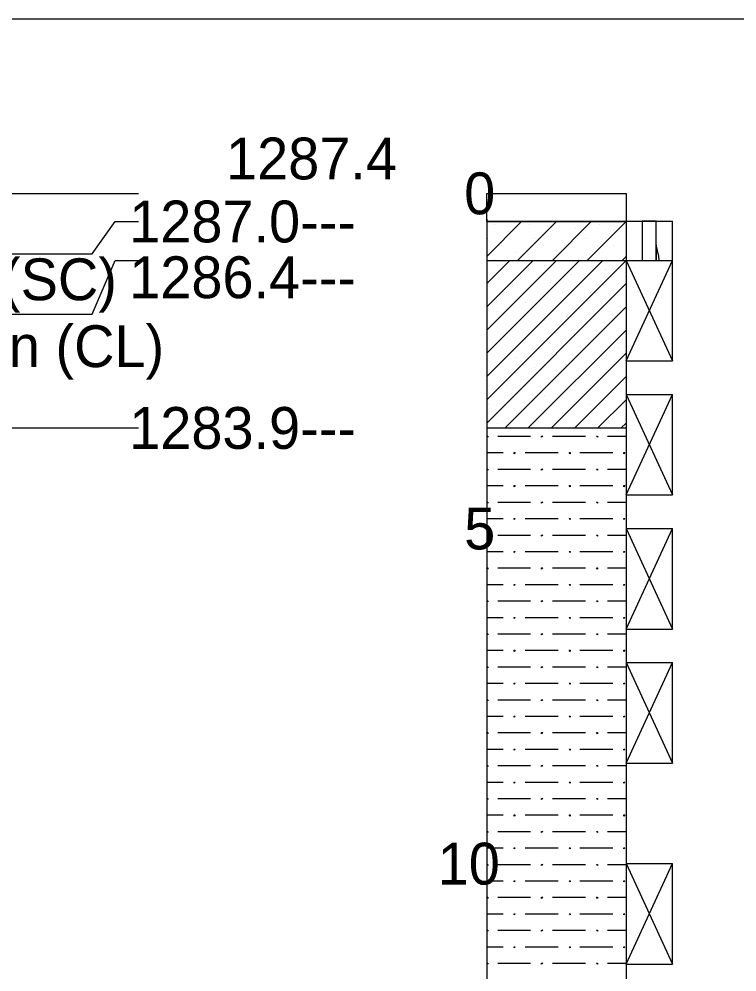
# Model space of a CAD drawing. Extents: x 2150148.6 to 2150220.1, y 143803.7 to 143875.1.
# Drawn here: x 2150200.808 to 2150203.385, y 143855.669 to 143859.086 of the extents above; entities that cross this region are included whole.
import ezdxf

# ---------------------------------------------------------------- set-up
doc = ezdxf.new("R2010")
doc.units = 0
doc.layers.add('Default', color=7, linetype='Continuous')

# ---------------------------------------------------------------- blocks, each defined once
blk = doc.blocks.new('POINT_DISPLAY')
at = {"layer": 'Default'}
blk.add_line((0, 0), (0, 0), dxfattribs=at)

msp = doc.modelspace()

# ---------------------------------------------------------------- linework, layer by layer
at = {"layer": 'Default'}
for points in [[(2150197.0699, 143858.4608), (2150201.2366, 143858.4608)], [(2150197.0699, 143858.3599), (2150197.1532, 143858.3599), (2150197.2366, 143858.2442), (2150201.0699, 143858.2442), (2150201.1532, 143858.3599), (2150201.2366, 143858.3599)], [(2150202.4866, 143858.3678), (2150202.4866, 143846.4416)], [(2150202.4866, 143858.3599), (2150202.9866, 143858.3599)], [(2150202.4866, 143858.2349), (2150202.6116, 143858.3599)], [(2150202.5971, 143858.2204), (2150202.7366, 143858.3599)], [(2150202.7221, 143858.2204), (2150202.8616, 143858.3599)], [(2150202.8471, 143858.2204), (2150202.9866, 143858.3599)], [(2150202.9866, 143858.3606), (2150203.1532, 143858.3606)], [(2150202.9866, 143858.3606), (2150202.9866, 143846.4416)], [(2150203.1532, 143858.2204), (2150203.1532, 143858.3606)], [(2150202.9721, 143858.2204), (2150202.9866, 143858.2349)], [(2150197.0699, 143858.2204), (2150197.1532, 143858.2204), (2150197.2366, 143858.0275), (2150201.0699, 143858.0275), (2150201.1532, 143858.2204), (2150201.2366, 143858.2204)], [(2150202.4866, 143858.2204), (2150202.9866, 143858.2204)], [(2150202.4866, 143858.1371), (2150202.5699, 143858.2204)], [(2150202.4866, 143858.0538), (2150202.6532, 143858.2204)], [(2150202.4866, 143857.9704), (2150202.7366, 143858.2204)], [(2150202.4866, 143857.8871), (2150202.8199, 143858.2204)], [(2150202.4866, 143857.8038), (2150202.9032, 143858.2204)], [(2150202.4866, 143857.7204), (2150202.9866, 143858.2204)], [(2150202.9866, 143858.2204), (2150203.1532, 143858.2204)], [(2150202.9866, 143858.2204), (2150203.1532, 143857.8599)], [(2150202.9866, 143857.8599), (2150203.1532, 143858.2204)], [(2150202.9866, 143858.2204), (2150203.1532, 143858.2204)], [(2150203.1532, 143857.8599), (2150203.1532, 143858.2204)], [(2150202.4866, 143857.6371), (2150202.9866, 143858.1371)], [(2150202.5523, 143857.6195), (2150202.9866, 143858.0538)], [(2150202.6356, 143857.6195), (2150202.9866, 143857.9704)], [(2150202.7189, 143857.6195), (2150202.9866, 143857.8871)], [(2150202.9866, 143857.8599), (2150203.1532, 143857.8599)], [(2150202.8023, 143857.6195), (2150202.9866, 143857.8038)], [(2150202.8856, 143857.6195), (2150202.9866, 143857.7204)], [(2150202.9866, 143857.7397), (2150203.1532, 143857.3791)], [(2150202.9866, 143857.3791), (2150203.1532, 143857.7397)], [(2150202.9866, 143857.7397), (2150203.1532, 143857.7397)], [(2150203.1532, 143857.3791), (2150203.1532, 143857.7397)], [(2150197.0699, 143857.6195), (2150201.2366, 143857.6195)], [(2150202.4866, 143857.6195), (2150202.9866, 143857.6195)], [(2150202.9689, 143857.6195), (2150202.9866, 143857.6371)], [(2150202.4866, 143857.59), (2150202.4905, 143857.59), (2150202.4905, 143857.586), (2150202.4866, 143857.59)], [(2150202.5259, 143857.59), (2150202.644, 143857.59)], [(2150202.6834, 143857.59), (2150202.6874, 143857.59), (2150202.6834, 143857.586), (2150202.6834, 143857.59)], [(2150202.7228, 143857.59), (2150202.8409, 143857.59)], [(2150202.8803, 143857.59), (2150202.8842, 143857.59), (2150202.8842, 143857.586), (2150202.8803, 143857.59)], [(2150202.9196, 143857.59), (2150202.9866, 143857.59)], [(2150202.4866, 143857.5309), (2150202.5456, 143857.5309)], [(2150202.585, 143857.5309), (2150202.5889, 143857.5309), (2150202.585, 143857.527), (2150202.585, 143857.5309)], [(2150202.6244, 143857.5309), (2150202.7425, 143857.5309)], [(2150202.7818, 143857.5309), (2150202.7858, 143857.5309), (2150202.7858, 143857.527), (2150202.7818, 143857.5309)], [(2150202.8212, 143857.5309), (2150202.8803, 143857.5309)], [(2150202.8803, 143857.5309), (2150202.9393, 143857.5309)], [(2150202.9787, 143857.5309), (2150202.9826, 143857.5309), (2150202.9787, 143857.527), (2150202.9787, 143857.5309)], [(2150202.4866, 143857.4718), (2150202.4905, 143857.4718), (2150202.4905, 143857.4679), (2150202.4866, 143857.4718)], [(2150202.5259, 143857.4718), (2150202.644, 143857.4718)], [(2150202.6834, 143857.4718), (2150202.6874, 143857.4718), (2150202.6834, 143857.4679), (2150202.6834, 143857.4718)], [(2150202.7228, 143857.4718), (2150202.8409, 143857.4718)], [(2150202.8803, 143857.4718), (2150202.8842, 143857.4718), (2150202.8842, 143857.4679), (2150202.8803, 143857.4718)], [(2150202.9196, 143857.4718), (2150202.9866, 143857.4718)], [(2150202.4866, 143857.4128), (2150202.5456, 143857.4128)], [(2150202.585, 143857.4128), (2150202.5889, 143857.4128), (2150202.585, 143857.4089), (2150202.585, 143857.4128)], [(2150202.6244, 143857.4128), (2150202.7425, 143857.4128)], [(2150202.7818, 143857.4128), (2150202.7858, 143857.4128), (2150202.7858, 143857.4089), (2150202.7818, 143857.4128)], [(2150202.8212, 143857.4128), (2150202.8803, 143857.4128)], [(2150202.8803, 143857.4128), (2150202.9393, 143857.4128)], [(2150202.9787, 143857.4128), (2150202.9826, 143857.4128), (2150202.9787, 143857.4089), (2150202.9787, 143857.4128)], [(2150202.9866, 143857.3791), (2150203.1532, 143857.3791)], [(2150202.4866, 143857.3537), (2150202.4905, 143857.3537), (2150202.4905, 143857.3498), (2150202.4866, 143857.3537)], [(2150202.5259, 143857.3537), (2150202.644, 143857.3537)], [(2150202.6834, 143857.3537), (2150202.6874, 143857.3537), (2150202.6834, 143857.3498), (2150202.6834, 143857.3537)], [(2150202.7228, 143857.3537), (2150202.8409, 143857.3537)], [(2150202.8803, 143857.3537), (2150202.8842, 143857.3537), (2150202.8842, 143857.3498), (2150202.8803, 143857.3537)], [(2150202.9196, 143857.3537), (2150202.9866, 143857.3537)], [(2150202.4866, 143857.2947), (2150202.5456, 143857.2947)], [(2150202.585, 143857.2947), (2150202.5889, 143857.2947), (2150202.585, 143857.2907), (2150202.585, 143857.2947)], [(2150202.6244, 143857.2947), (2150202.7425, 143857.2947)], [(2150202.7818, 143857.2947), (2150202.7858, 143857.2947), (2150202.7858, 143857.2907), (2150202.7818, 143857.2947)], [(2150202.8212, 143857.2947), (2150202.8803, 143857.2947)], [(2150202.8803, 143857.2947), (2150202.9393, 143857.2947)], [(2150202.9787, 143857.2947), (2150202.9826, 143857.2947), (2150202.9787, 143857.2907), (2150202.9787, 143857.2947)], [(2150202.9866, 143857.2589), (2150203.1532, 143856.8983)], [(2150202.9866, 143856.8983), (2150203.1532, 143857.2589)], [(2150202.9866, 143857.2589), (2150203.1532, 143857.2589)], [(2150203.1532, 143856.8983), (2150203.1532, 143857.2589)], [(2150202.4866, 143857.2356), (2150202.4905, 143857.2356), (2150202.4905, 143857.2317), (2150202.4866, 143857.2356)], [(2150202.5259, 143857.2356), (2150202.644, 143857.2356)], [(2150202.6834, 143857.2356), (2150202.6874, 143857.2356), (2150202.6834, 143857.2317), (2150202.6834, 143857.2356)], [(2150202.7228, 143857.2356), (2150202.8409, 143857.2356)], [(2150202.8803, 143857.2356), (2150202.8842, 143857.2356), (2150202.8842, 143857.2317), (2150202.8803, 143857.2356)], [(2150202.9196, 143857.2356), (2150202.9866, 143857.2356)], [(2150202.4866, 143857.1766), (2150202.5456, 143857.1766)], [(2150202.585, 143857.1766), (2150202.5889, 143857.1766), (2150202.585, 143857.1726), (2150202.585, 143857.1766)], [(2150202.6244, 143857.1766), (2150202.7425, 143857.1766)], [(2150202.7818, 143857.1766), (2150202.7858, 143857.1766), (2150202.7858, 143857.1726), (2150202.7818, 143857.1766)], [(2150202.8212, 143857.1766), (2150202.8803, 143857.1766)], [(2150202.8803, 143857.1766), (2150202.9393, 143857.1766)], [(2150202.9787, 143857.1766), (2150202.9826, 143857.1766), (2150202.9787, 143857.1726), (2150202.9787, 143857.1766)], [(2150202.4866, 143857.1175), (2150202.4905, 143857.1175), (2150202.4905, 143857.1136), (2150202.4866, 143857.1175)], [(2150202.5259, 143857.1175), (2150202.644, 143857.1175)], [(2150202.6834, 143857.1175), (2150202.6874, 143857.1175), (2150202.6834, 143857.1136), (2150202.6834, 143857.1175)], [(2150202.7228, 143857.1175), (2150202.8409, 143857.1175)], [(2150202.8803, 143857.1175), (2150202.8842, 143857.1175), (2150202.8842, 143857.1136), (2150202.8803, 143857.1175)], [(2150202.9196, 143857.1175), (2150202.9866, 143857.1175)], [(2150202.4866, 143857.0585), (2150202.5456, 143857.0585)], [(2150202.585, 143857.0585), (2150202.5889, 143857.0585), (2150202.585, 143857.0545), (2150202.585, 143857.0585)], [(2150202.6244, 143857.0585), (2150202.7425, 143857.0585)], [(2150202.7818, 143857.0585), (2150202.7858, 143857.0585), (2150202.7858, 143857.0545), (2150202.7818, 143857.0585)], [(2150202.8212, 143857.0585), (2150202.8803, 143857.0585)], [(2150202.8803, 143857.0585), (2150202.9393, 143857.0585)], [(2150202.9787, 143857.0585), (2150202.9826, 143857.0585), (2150202.9787, 143857.0545), (2150202.9787, 143857.0585)], [(2150202.4866, 143856.9994), (2150202.4905, 143856.9994), (2150202.4905, 143856.9955), (2150202.4866, 143856.9994)], [(2150202.5259, 143856.9994), (2150202.644, 143856.9994)], [(2150202.6834, 143856.9994), (2150202.6874, 143856.9994), (2150202.6834, 143856.9955), (2150202.6834, 143856.9994)], [(2150202.7228, 143856.9994), (2150202.8409, 143856.9994)], [(2150202.8803, 143856.9994), (2150202.8842, 143856.9994), (2150202.8842, 143856.9955), (2150202.8803, 143856.9994)], [(2150202.9196, 143856.9994), (2150202.9866, 143856.9994)], [(2150202.4866, 143856.9403), (2150202.5456, 143856.9403)], [(2150202.585, 143856.9403), (2150202.5889, 143856.9403), (2150202.585, 143856.9364), (2150202.585, 143856.9403)], [(2150202.6244, 143856.9403), (2150202.7425, 143856.9403)], [(2150202.7818, 143856.9403), (2150202.7858, 143856.9403), (2150202.7858, 143856.9364), (2150202.7818, 143856.9403)], [(2150202.8212, 143856.9403), (2150202.8803, 143856.9403)], [(2150202.8803, 143856.9403), (2150202.9393, 143856.9403)], [(2150202.9787, 143856.9403), (2150202.9826, 143856.9403), (2150202.9787, 143856.9364), (2150202.9787, 143856.9403)], [(2150202.4866, 143856.8813), (2150202.4905, 143856.8813), (2150202.4905, 143856.8774), (2150202.4866, 143856.8813)], [(2150202.5259, 143856.8813), (2150202.644, 143856.8813)], [(2150202.6834, 143856.8813), (2150202.6874, 143856.8813), (2150202.6834, 143856.8774), (2150202.6834, 143856.8813)], [(2150202.7228, 143856.8813), (2150202.8409, 143856.8813)], [(2150202.8803, 143856.8813), (2150202.8842, 143856.8813), (2150202.8842, 143856.8774), (2150202.8803, 143856.8813)], [(2150202.9196, 143856.8813), (2150202.9866, 143856.8813)], [(2150202.9866, 143856.8983), (2150203.1532, 143856.8983)], [(2150202.4866, 143856.8222), (2150202.5456, 143856.8222)], [(2150202.585, 143856.8222), (2150202.5889, 143856.8222), (2150202.585, 143856.8183), (2150202.585, 143856.8222)], [(2150202.6244, 143856.8222), (2150202.7425, 143856.8222)], [(2150202.7818, 143856.8222), (2150202.7858, 143856.8222), (2150202.7858, 143856.8183), (2150202.7818, 143856.8222)], [(2150202.8212, 143856.8222), (2150202.8803, 143856.8222)], [(2150202.8803, 143856.8222), (2150202.9393, 143856.8222)], [(2150202.9787, 143856.8222), (2150202.9826, 143856.8222), (2150202.9787, 143856.8183), (2150202.9787, 143856.8222)], [(2150202.9866, 143856.7781), (2150203.1532, 143856.4176)], [(2150202.9866, 143856.4176), (2150203.1532, 143856.7781)], [(2150202.9866, 143856.7781), (2150203.1532, 143856.7781)], [(2150203.1532, 143856.4176), (2150203.1532, 143856.7781)], [(2150202.4866, 143856.7632), (2150202.4905, 143856.7632), (2150202.4905, 143856.7592), (2150202.4866, 143856.7632)], [(2150202.5259, 143856.7632), (2150202.644, 143856.7632)], [(2150202.6834, 143856.7632), (2150202.6874, 143856.7632), (2150202.6834, 143856.7592), (2150202.6834, 143856.7632)], [(2150202.7228, 143856.7632), (2150202.8409, 143856.7632)], [(2150202.8803, 143856.7632), (2150202.8842, 143856.7632), (2150202.8842, 143856.7592), (2150202.8803, 143856.7632)], [(2150202.9196, 143856.7632), (2150202.9866, 143856.7632)], [(2150202.4866, 143856.7041), (2150202.5456, 143856.7041)], [(2150202.585, 143856.7041), (2150202.5889, 143856.7041), (2150202.585, 143856.7002), (2150202.585, 143856.7041)], [(2150202.6244, 143856.7041), (2150202.7425, 143856.7041)], [(2150202.7818, 143856.7041), (2150202.7858, 143856.7041), (2150202.7858, 143856.7002), (2150202.7818, 143856.7041)], [(2150202.8212, 143856.7041), (2150202.8803, 143856.7041)], [(2150202.8803, 143856.7041), (2150202.9393, 143856.7041)], [(2150202.9787, 143856.7041), (2150202.9826, 143856.7041), (2150202.9787, 143856.7002), (2150202.9787, 143856.7041)], [(2150202.4866, 143856.6451), (2150202.4905, 143856.6451), (2150202.4905, 143856.6411), (2150202.4866, 143856.6451)], [(2150202.5259, 143856.6451), (2150202.644, 143856.6451)], [(2150202.6834, 143856.6451), (2150202.6874, 143856.6451), (2150202.6834, 143856.6411), (2150202.6834, 143856.6451)], [(2150202.7228, 143856.6451), (2150202.8409, 143856.6451)], [(2150202.8803, 143856.6451), (2150202.8842, 143856.6451), (2150202.8842, 143856.6411), (2150202.8803, 143856.6451)], [(2150202.9196, 143856.6451), (2150202.9866, 143856.6451)], [(2150202.4866, 143856.586), (2150202.5456, 143856.586)], [(2150202.585, 143856.586), (2150202.5889, 143856.586), (2150202.585, 143856.5821), (2150202.585, 143856.586)], [(2150202.6244, 143856.586), (2150202.7425, 143856.586)], [(2150202.7818, 143856.586), (2150202.7858, 143856.586), (2150202.7858, 143856.5821), (2150202.7818, 143856.586)], [(2150202.8212, 143856.586), (2150202.8803, 143856.586)], [(2150202.8803, 143856.586), (2150202.9393, 143856.586)], [(2150202.9787, 143856.586), (2150202.9826, 143856.586), (2150202.9787, 143856.5821), (2150202.9787, 143856.586)], [(2150202.4866, 143856.527), (2150202.4905, 143856.527), (2150202.4905, 143856.523), (2150202.4866, 143856.527)], [(2150202.5259, 143856.527), (2150202.644, 143856.527)], [(2150202.6834, 143856.527), (2150202.6874, 143856.527), (2150202.6834, 143856.523), (2150202.6834, 143856.527)], [(2150202.7228, 143856.527), (2150202.8409, 143856.527)], [(2150202.8803, 143856.527), (2150202.8842, 143856.527), (2150202.8842, 143856.523), (2150202.8803, 143856.527)], [(2150202.9196, 143856.527), (2150202.9866, 143856.527)], [(2150202.4866, 143856.4679), (2150202.5456, 143856.4679)], [(2150202.585, 143856.4679), (2150202.5889, 143856.4679), (2150202.585, 143856.464), (2150202.585, 143856.4679)], [(2150202.6244, 143856.4679), (2150202.7425, 143856.4679)], [(2150202.7818, 143856.4679), (2150202.7858, 143856.4679), (2150202.7858, 143856.464), (2150202.7818, 143856.4679)], [(2150202.8212, 143856.4679), (2150202.8803, 143856.4679)], [(2150202.8803, 143856.4679), (2150202.9393, 143856.4679)], [(2150202.9787, 143856.4679), (2150202.9826, 143856.4679), (2150202.9787, 143856.464), (2150202.9787, 143856.4679)], [(2150202.4866, 143856.4089), (2150202.4905, 143856.4089), (2150202.4905, 143856.4049), (2150202.4866, 143856.4089)], [(2150202.5259, 143856.4089), (2150202.644, 143856.4089)], [(2150202.6834, 143856.4089), (2150202.6874, 143856.4089), (2150202.6834, 143856.4049), (2150202.6834, 143856.4089)], [(2150202.7228, 143856.4089), (2150202.8409, 143856.4089)], [(2150202.8803, 143856.4089), (2150202.8842, 143856.4089), (2150202.8842, 143856.4049), (2150202.8803, 143856.4089)], [(2150202.9196, 143856.4089), (2150202.9866, 143856.4089)], [(2150202.9866, 143856.4176), (2150203.1532, 143856.4176)], [(2150202.4866, 143856.3498), (2150202.5456, 143856.3498)], [(2150202.585, 143856.3498), (2150202.5889, 143856.3498), (2150202.585, 143856.3459), (2150202.585, 143856.3498)], [(2150202.6244, 143856.3498), (2150202.7425, 143856.3498)], [(2150202.7818, 143856.3498), (2150202.7858, 143856.3498), (2150202.7858, 143856.3459), (2150202.7818, 143856.3498)], [(2150202.8212, 143856.3498), (2150202.8803, 143856.3498)], [(2150202.8803, 143856.3498), (2150202.9393, 143856.3498)], [(2150202.9787, 143856.3498), (2150202.9826, 143856.3498), (2150202.9787, 143856.3459), (2150202.9787, 143856.3498)], [(2150202.4866, 143856.2907), (2150202.4905, 143856.2907), (2150202.4905, 143856.2868), (2150202.4866, 143856.2907)], [(2150202.5259, 143856.2907), (2150202.644, 143856.2907)], [(2150202.6834, 143856.2907), (2150202.6874, 143856.2907), (2150202.6834, 143856.2868), (2150202.6834, 143856.2907)], [(2150202.7228, 143856.2907), (2150202.8409, 143856.2907)], [(2150202.8803, 143856.2907), (2150202.8842, 143856.2907), (2150202.8842, 143856.2868), (2150202.8803, 143856.2907)], [(2150202.9196, 143856.2907), (2150202.9866, 143856.2907)], [(2150202.4866, 143856.2317), (2150202.5456, 143856.2317)], [(2150202.585, 143856.2317), (2150202.5889, 143856.2317), (2150202.585, 143856.2278), (2150202.585, 143856.2317)], [(2150202.6244, 143856.2317), (2150202.7425, 143856.2317)], [(2150202.7818, 143856.2317), (2150202.7858, 143856.2317), (2150202.7858, 143856.2278), (2150202.7818, 143856.2317)], [(2150202.8212, 143856.2317), (2150202.8803, 143856.2317)], [(2150202.8803, 143856.2317), (2150202.9393, 143856.2317)], [(2150202.9787, 143856.2317), (2150202.9826, 143856.2317), (2150202.9787, 143856.2278), (2150202.9787, 143856.2317)], [(2150202.4866, 143856.1726), (2150202.4905, 143856.1726), (2150202.4905, 143856.1687), (2150202.4866, 143856.1726)], [(2150202.5259, 143856.1726), (2150202.644, 143856.1726)], [(2150202.6834, 143856.1726), (2150202.6874, 143856.1726), (2150202.6834, 143856.1687), (2150202.6834, 143856.1726)], [(2150202.7228, 143856.1726), (2150202.8409, 143856.1726)], [(2150202.8803, 143856.1726), (2150202.8842, 143856.1726), (2150202.8842, 143856.1687), (2150202.8803, 143856.1726)], [(2150202.9196, 143856.1726), (2150202.9866, 143856.1726)], [(2150202.4866, 143856.1136), (2150202.5456, 143856.1136)], [(2150202.585, 143856.1136), (2150202.5889, 143856.1136), (2150202.585, 143856.1096), (2150202.585, 143856.1136)], [(2150202.6244, 143856.1136), (2150202.7425, 143856.1136)], [(2150202.7818, 143856.1136), (2150202.7858, 143856.1136), (2150202.7858, 143856.1096), (2150202.7818, 143856.1136)], [(2150202.8212, 143856.1136), (2150202.8803, 143856.1136)], [(2150202.8803, 143856.1136), (2150202.9393, 143856.1136)], [(2150202.9787, 143856.1136), (2150202.9826, 143856.1136), (2150202.9787, 143856.1096), (2150202.9787, 143856.1136)], [(2150202.4866, 143856.0545), (2150202.4905, 143856.0545), (2150202.4905, 143856.0506), (2150202.4866, 143856.0545)], [(2150202.5259, 143856.0545), (2150202.644, 143856.0545)], [(2150202.6834, 143856.0545), (2150202.6874, 143856.0545), (2150202.6834, 143856.0506), (2150202.6834, 143856.0545)], [(2150202.7228, 143856.0545), (2150202.8409, 143856.0545)], [(2150202.8803, 143856.0545), (2150202.8842, 143856.0545), (2150202.8842, 143856.0506), (2150202.8803, 143856.0545)], [(2150202.9196, 143856.0545), (2150202.9866, 143856.0545)], [(2150202.9866, 143856.057), (2150203.1532, 143855.6964)], [(2150202.9866, 143855.6964), (2150203.1532, 143856.057)], [(2150202.9866, 143856.057), (2150203.1532, 143856.057)], [(2150203.1532, 143855.6964), (2150203.1532, 143856.057)], [(2150202.4866, 143855.9955), (2150202.5456, 143855.9955)], [(2150202.585, 143855.9955), (2150202.5889, 143855.9955), (2150202.585, 143855.9915), (2150202.585, 143855.9955)], [(2150202.6244, 143855.9955), (2150202.7425, 143855.9955)], [(2150202.7818, 143855.9955), (2150202.7858, 143855.9955), (2150202.7858, 143855.9915), (2150202.7818, 143855.9955)], [(2150202.8212, 143855.9955), (2150202.8803, 143855.9955)], [(2150202.8803, 143855.9955), (2150202.9393, 143855.9955)], [(2150202.9787, 143855.9955), (2150202.9826, 143855.9955), (2150202.9787, 143855.9915), (2150202.9787, 143855.9955)], [(2150202.4866, 143855.9364), (2150202.4905, 143855.9364), (2150202.4905, 143855.9325), (2150202.4866, 143855.9364)], [(2150202.5259, 143855.9364), (2150202.644, 143855.9364)], [(2150202.6834, 143855.9364), (2150202.6874, 143855.9364), (2150202.6834, 143855.9325), (2150202.6834, 143855.9364)], [(2150202.7228, 143855.9364), (2150202.8409, 143855.9364)], [(2150202.8803, 143855.9364), (2150202.8842, 143855.9364), (2150202.8842, 143855.9325), (2150202.8803, 143855.9364)], [(2150202.9196, 143855.9364), (2150202.9866, 143855.9364)], [(2150202.4866, 143855.8774), (2150202.5456, 143855.8774)], [(2150202.585, 143855.8774), (2150202.5889, 143855.8774), (2150202.585, 143855.8734), (2150202.585, 143855.8774)], [(2150202.6244, 143855.8774), (2150202.7425, 143855.8774)], [(2150202.7818, 143855.8774), (2150202.7858, 143855.8774), (2150202.7858, 143855.8734), (2150202.7818, 143855.8774)], [(2150202.8212, 143855.8774), (2150202.8803, 143855.8774)], [(2150202.8803, 143855.8774), (2150202.9393, 143855.8774)], [(2150202.9787, 143855.8774), (2150202.9826, 143855.8774), (2150202.9787, 143855.8734), (2150202.9787, 143855.8774)], [(2150202.4866, 143855.8183), (2150202.4905, 143855.8183), (2150202.4905, 143855.8144), (2150202.4866, 143855.8183)], [(2150202.5259, 143855.8183), (2150202.644, 143855.8183)], [(2150202.6834, 143855.8183), (2150202.6874, 143855.8183), (2150202.6834, 143855.8144), (2150202.6834, 143855.8183)], [(2150202.7228, 143855.8183), (2150202.8409, 143855.8183)], [(2150202.8803, 143855.8183), (2150202.8842, 143855.8183), (2150202.8842, 143855.8144), (2150202.8803, 143855.8183)], [(2150202.9196, 143855.8183), (2150202.9866, 143855.8183)], [(2150202.4866, 143855.7592), (2150202.5456, 143855.7592)], [(2150202.585, 143855.7592), (2150202.5889, 143855.7592), (2150202.585, 143855.7553), (2150202.585, 143855.7592)], [(2150202.6244, 143855.7592), (2150202.7425, 143855.7592)], [(2150202.7818, 143855.7592), (2150202.7858, 143855.7592), (2150202.7858, 143855.7553), (2150202.7818, 143855.7592)], [(2150202.8212, 143855.7592), (2150202.8803, 143855.7592)], [(2150202.8803, 143855.7592), (2150202.9393, 143855.7592)], [(2150202.9787, 143855.7592), (2150202.9826, 143855.7592), (2150202.9787, 143855.7553), (2150202.9787, 143855.7592)], [(2150202.4866, 143855.7002), (2150202.4905, 143855.7002), (2150202.4905, 143855.6963), (2150202.4866, 143855.7002)], [(2150202.5259, 143855.7002), (2150202.644, 143855.7002)], [(2150202.6834, 143855.7002), (2150202.6874, 143855.7002), (2150202.6834, 143855.6963), (2150202.6834, 143855.7002)], [(2150202.7228, 143855.7002), (2150202.8409, 143855.7002)], [(2150202.8803, 143855.7002), (2150202.8842, 143855.7002), (2150202.8842, 143855.6963), (2150202.8803, 143855.7002)], [(2150202.9196, 143855.7002), (2150202.9866, 143855.7002)], [(2150202.9866, 143855.6964), (2150203.1532, 143855.6964)]]:
    msp.add_lwpolyline(points, dxfattribs=at)
for points in [[(2150202.4866, 143858.3599), (2150202.4866, 143858.4608), (2150202.9866, 143858.4608), (2150202.9866, 143858.3599)], [(2150203.0449, 143858.3606), (2150203.0449, 143858.2204), (2150203.0949, 143858.2204), (2150203.0949, 143858.3606)], [(2150203.1036, 143858.2356), (2150203.0949, 143858.2756), (2150203.0949, 143858.2204), (2150203.1057, 143858.2204)]]:
    msp.add_lwpolyline(points, close=True, dxfattribs=at)
at = {"layer": 'Defpoints'}
msp.add_line((2150210.3791, 143859.0858), (2150168.3792, 143859.0858), dxfattribs=at)

# ---------------------------------------------------------------- block references
at = {"layer": 'Default', "xscale": 0.39369999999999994, "yscale": 0.3936999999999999}
for p in [(2150202.5159, 143858.3474), (2150202.6409, 143858.3474), (2150202.8909, 143858.3474), (2150202.5659, 143858.3224), (2150202.7159, 143858.3224), (2150202.8057, 143858.3349), (2150202.9659, 143858.3224), (2150202.4909, 143858.2974), (2150202.5409, 143858.2724), (2150202.6581, 143858.2996), (2150202.6909, 143858.2724), (2150202.7659, 143858.2724), (2150202.8409, 143858.2974), (2150202.9409, 143858.2724), (2150202.5909, 143858.2474), (2150202.8909, 143858.2474), (2150202.5159, 143858.2224), (2150202.5257, 143858.2038), (2150202.6924, 143858.2038), (2150202.8159, 143858.2224), (2150202.5924, 143858.1704), (2150202.7924, 143858.1704), (2150202.9121, 143858.1871), (2150202.4924, 143858.1371), (2150202.7153, 143858.1401), (2150202.9591, 143858.1371), (2150202.5591, 143858.1038), (2150202.7591, 143858.1038), (2150202.8591, 143858.1038), (2150202.6257, 143858.0704), (2150202.5257, 143858.0371), (2150202.7759, 143858.028), (2150202.9257, 143858.0371), (2150202.6924, 143858.0038), (2150202.5591, 143857.9704), (2150202.7924, 143857.9704), (2150202.6257, 143857.9371), (2150202.7108, 143857.9265), (2150202.9106, 143857.9523), (2150202.4924, 143857.9038), (2150202.9591, 143857.9038), (2150202.5924, 143857.8704), (2150202.8257, 143857.8704), (2150202.6591, 143857.8371), (2150202.7623, 143857.8568), (2150202.8924, 143857.8371), (2150202.7257, 143857.8038), (2150202.5591, 143857.7704), (2150202.8047, 143857.7704), (2150202.9257, 143857.7704), (2150202.6924, 143857.7371), (2150202.4924, 143857.7038), (2150202.8591, 143857.7038), (2150202.5924, 143857.6704), (2150202.7591, 143857.6704), (2150202.5257, 143857.6371), (2150202.9257, 143857.6371)]:
    msp.add_blockref('POINT_DISPLAY', p, dxfattribs=at)

# ---------------------------------------------------------------- texts
at = {"layer": 'Default'}
for s, p in [('1287.4', (2150201.5509, 143858.5108)), ('0', (2150202.4056, 143858.3858)), ('1287.0---', (2150201.2032, 143858.2849)), ('Silty, Clayey SAND with Gravel, brown (SC)', (2150197.2578, 143858.0775)), ('1286.4---', (2150201.2032, 143858.0849)), ('Lean CLAY with Sand, medium stiff, brown (CL)', (2150197.0699, 143857.8376)), ('1283.9---', (2150201.2032, 143857.5445)), ('5', (2150202.4056, 143857.1839)), ('10', (2150202.3104, 143855.982))]:
    msp.add_text(s, height=0.15, dxfattribs=at).set_placement(p)

doc.saveas('drawing.dxf')
